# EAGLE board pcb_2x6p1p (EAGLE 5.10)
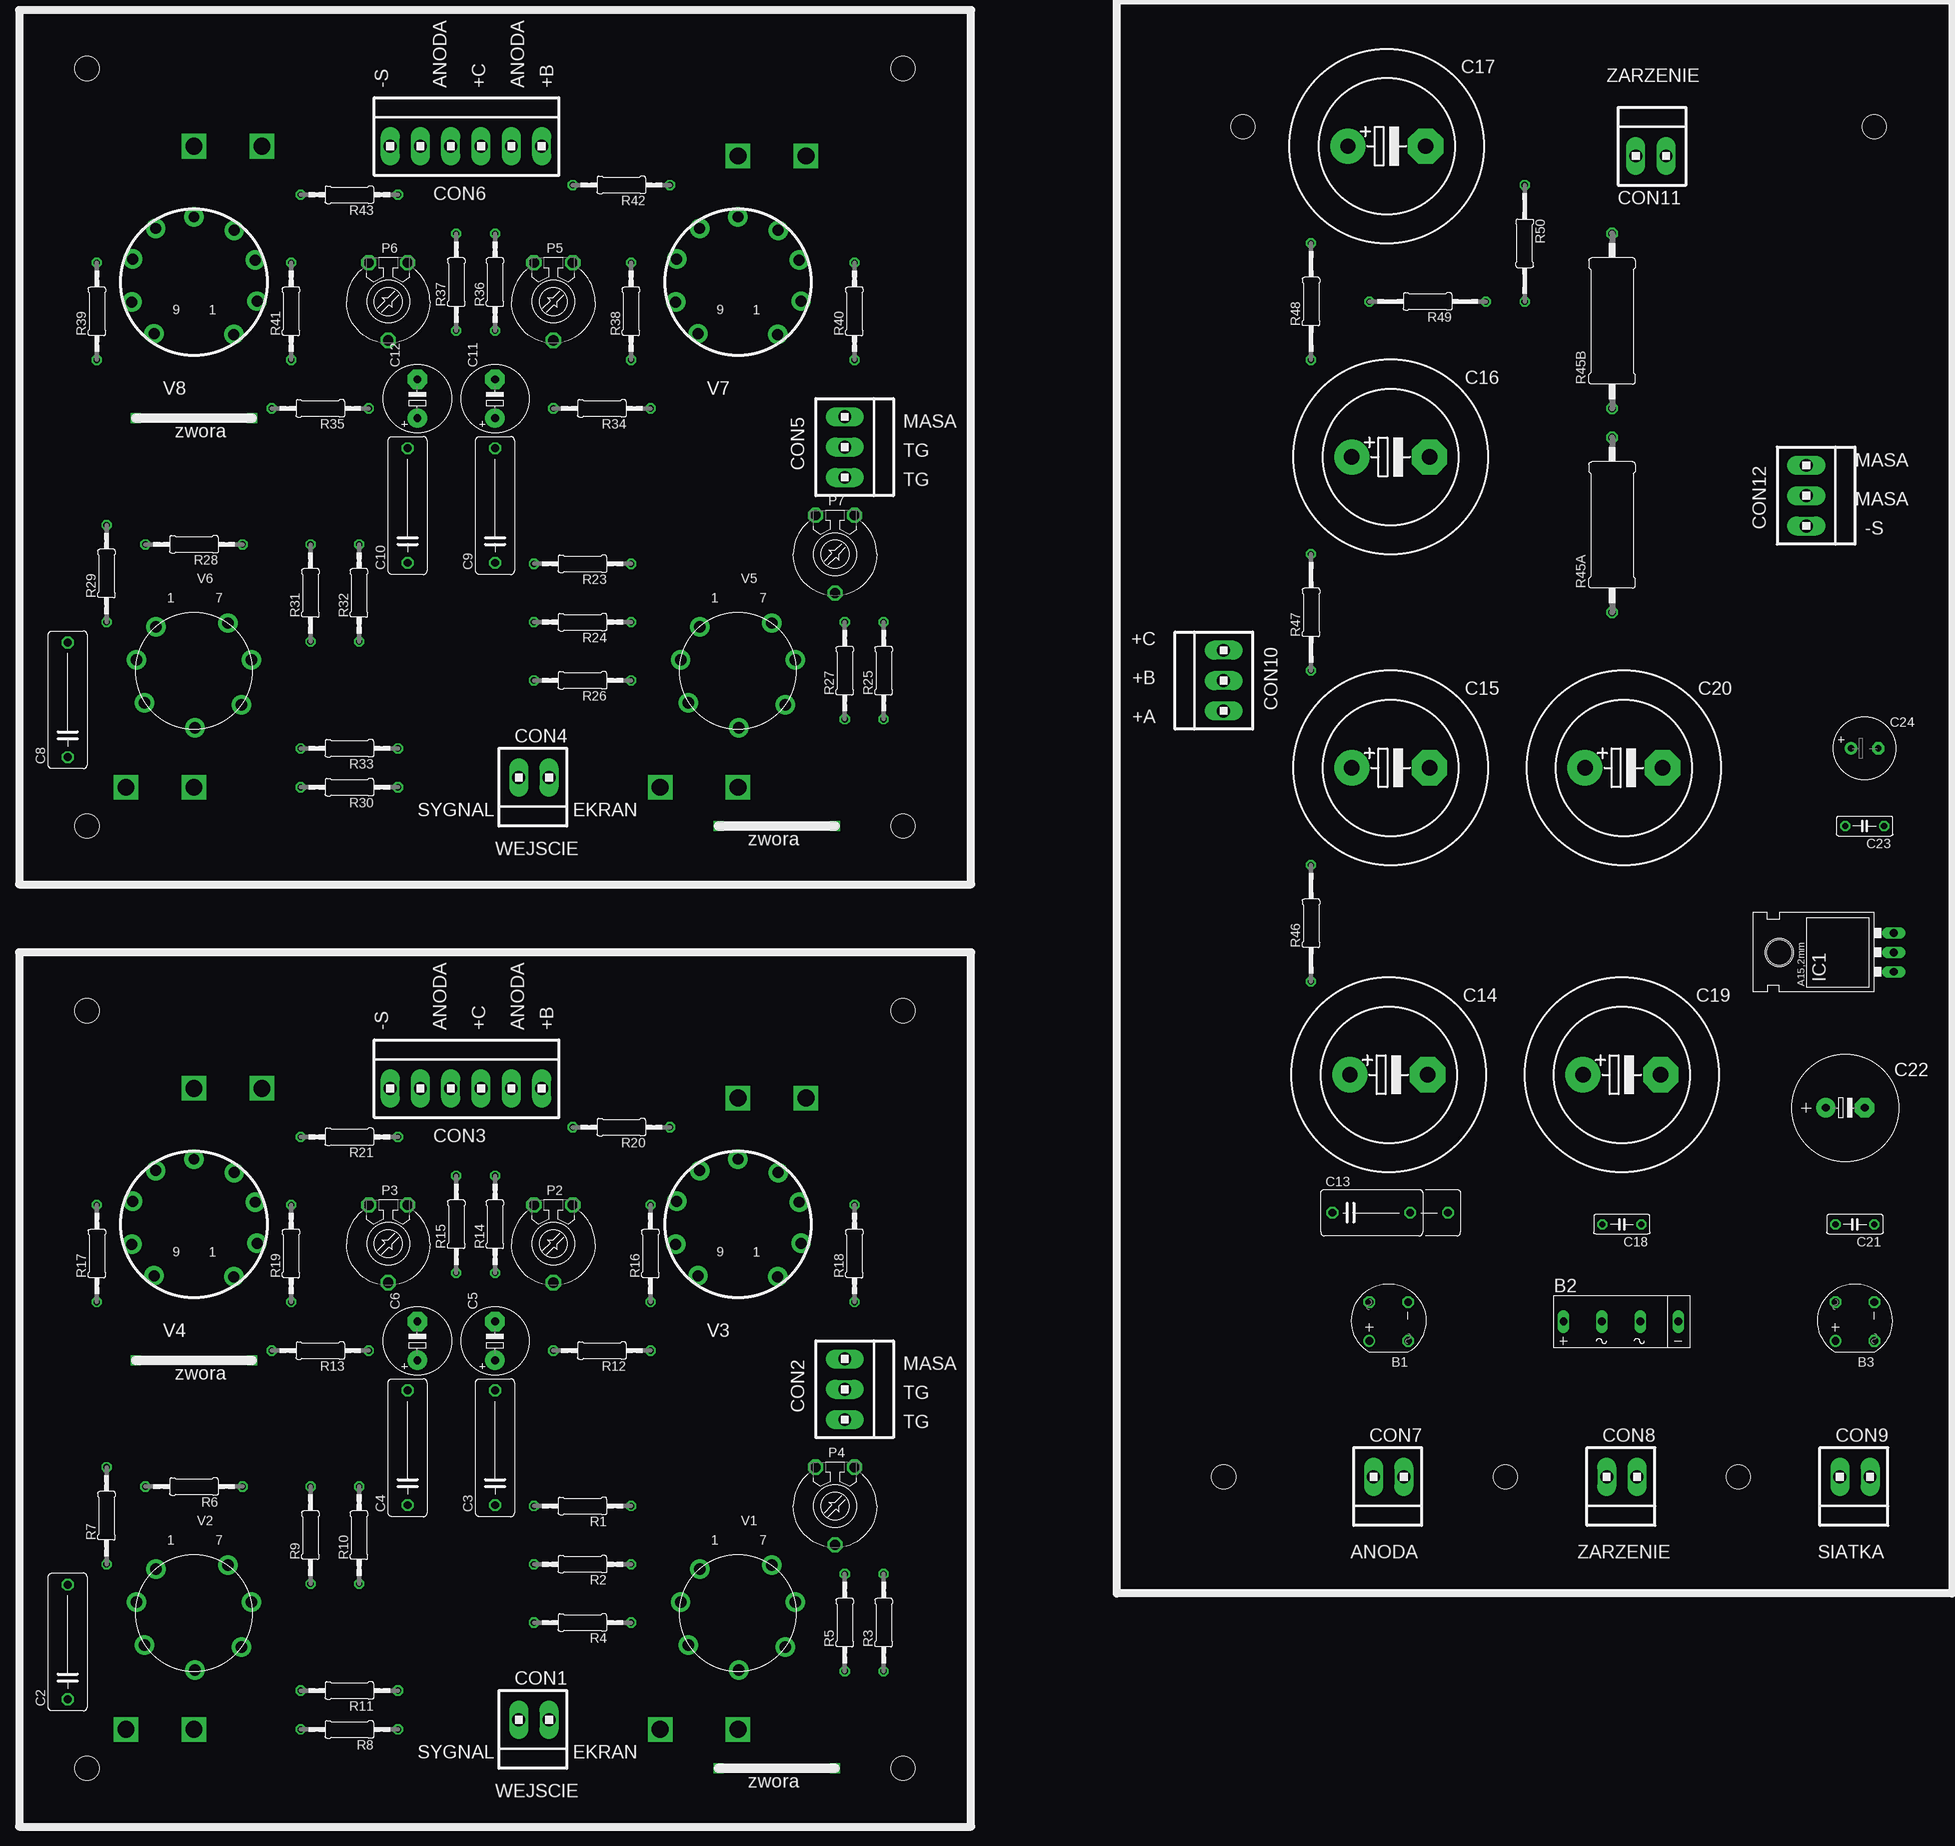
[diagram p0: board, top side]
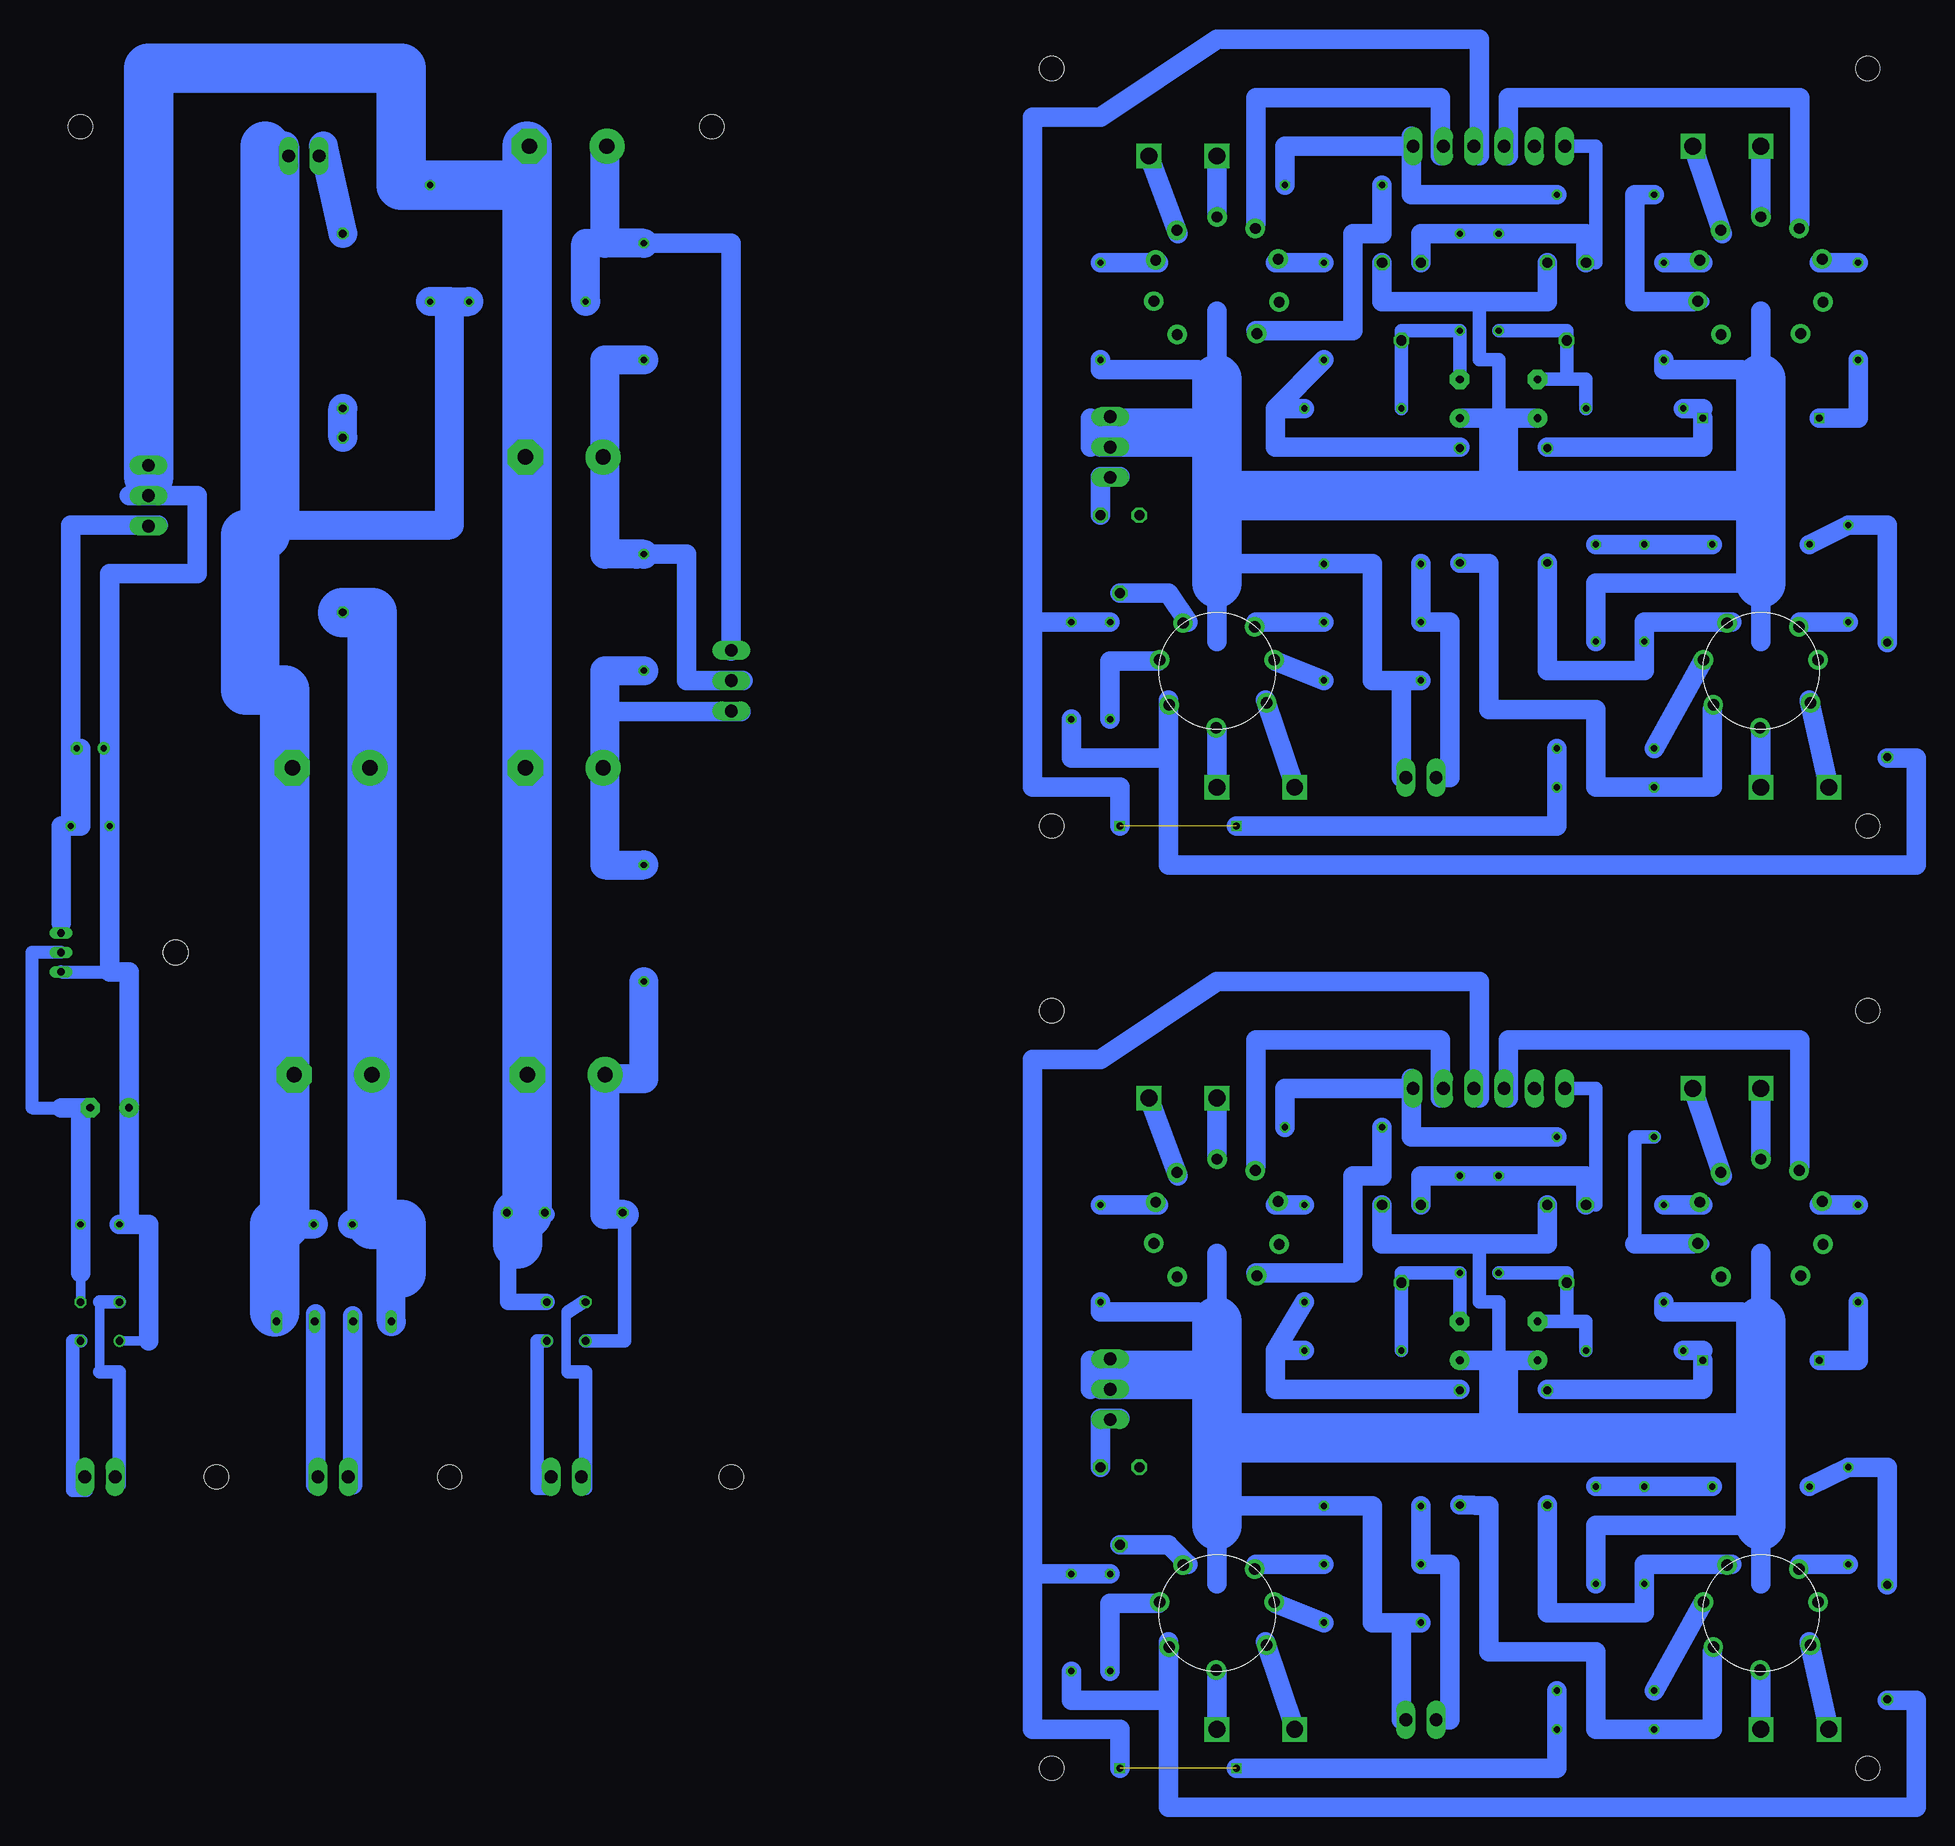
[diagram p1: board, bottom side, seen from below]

No outline drawn. Coordinates in mm, seen from the top.
Copper layers (1*16): Top 0.035mm / dielectric 1.5mm / Bottom 0.035mm
Design rules "default": minimum track width 10mil, minimum drill 24mil, track to track 8mil, track to pad 8mil, pad to pad 8mil, via to via 8mil, smd to smd 8mil, copper to edge 40mil, drill to drill 8mil, minimum pad ring 10mil, minimum via ring 8mil, stop-mask expansion 4mil, vias tented up to drill 0mil, thermal gap 10mil
Holes 3.2 mm at 116.84,12.7 10.16,111.76 116.84,111.76 10.16,12.7 116.84,135.89 10.16,234.95 116.84,234.95 10.16,135.89 195.58,50.8 226.06,50.8 243.84,227.33 161.29,227.33 158.75,50.8

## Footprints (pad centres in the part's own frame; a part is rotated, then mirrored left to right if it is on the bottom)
RB1A = drill 1.016 round: + -2.54,2.54 | drill 1.016 octagon: - 2.54,-2.54; AC1 2.54,2.54; AC2 -2.54,-2.54
2KBB-R = drill 1.016 long: + -7.62,0; - 7.391,0; AC1 -2.616,0; AC2 2.413,0
C150-054X183 = drill 1.016 octagon: 1 -7.493,0; 2 7.493,0
E5-8,5 = drill 1.016 pad 2.54 round: + -2.54,0 | drill 1.016 pad 2.54 octagon: - 2.54,0
C102_152-062X184 = drill 1.016 octagon: 1 -5.08,0; 2 5.08,0; 3 10.033,0
EB25D = drill 2.007 pad 4.597 round: + -5.08,0 | drill 2.007 pad 4.597 octagon: - 5.08,0
C050-025X075 = drill 0.813 octagon: 1 -2.54,0; 2 2.54,0
E5-13 = drill 1.016 pad 2.54 round: + -2.54,0 | drill 1.016 pad 2.54 octagon: - 2.54,0
E3,5-8 = drill 0.813 pad 1.6 round: + -1.778,0 | drill 0.813 pad 1.6 octagon: - 1.778,0
1X2MTA = drill 1.676 long: 1 1.981,0; 2 -1.981,0
1X3MTA = drill 1.676 long: 1 3.937,0; 2 -0.025,0; 3 -3.988,0
1X6MTA = drill 1.676 long: 1 9.906,0; 2 5.944,0; 3 1.981,0; 4 -1.981,0; 5 -5.944,0; 6 -9.906,0
79XXL = drill 1.016 long: GND -2.54,-3.81; IN 0,-3.81; OUT 2.54,-3.81 | hole 3.302: 0,11.176
LI10 = drill 1.321 octagon: A -2.54,-5.08; E 2.54,-5.08; S 0,5.08
0207/12 = drill 0.813 octagon: 1 -6.35,0; 2 6.35,0
0617/22 = drill 1.016 octagon: 1 -11.43,0; 2 11.43,0
0207/15 = drill 0.813 octagon: 1 -7.62,0; 2 7.62,0
MINI7_PCB = drill 1.5 pad 2.54 round: 2 4.953,-5.715; 3 7.493,-1.397; 4 6.477,4.191; 5 -0.127,7.493; 6 -6.223,4.445; 7 -4.445,-6.223; 8 -7.493,-1.397
NOVAL = drill 1.422 pad 2.54 round: 1 5.207,-6.858; 2 8.254,-2.484; 3 8.004,2.893; 4 5.258,6.77; 5 0,8.524; 6 -5.004,7.024; 7 -8.004,3.02; 8 -8.127,-2.611; 9 -5.207,-6.731

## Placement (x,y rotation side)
B1  [RB1A]  180.34,71.12 90 top
B2  [2KBB-R]  210.82,71.12 0 top
B3  [RB1A]  241.3,71.12 90 top
C2  [C150-054X183]  7.62,29.21 90 top
C3  [C150-054X183]  63.5,54.61 90 top
C4  [C150-054X183]  52.07,54.61 90 top
C5  [E5-8,5]  63.5,68.58 90 top
C6  [E5-8,5]  53.34,68.58 90 top
C8  [C150-054X183]  7.62,152.4 90 top
C9  [C150-054X183]  63.5,177.8 90 top
C10  [C150-054X183]  52.07,177.8 90 top
C11  [E5-8,5]  63.5,191.77 90 top
C12  [E5-8,5]  53.34,191.77 90 top
C13  [C102_152-062X184]  178.05,85.34 0 top
C14  [EB25D]  180.34,103.38 0 top
C15  [EB25D]  180.59,143.51 0 top
C16  [EB25D]  180.59,184.15 0 top
C17  [EB25D]  180.09,224.79 0 top
C18  [C050-025X075]  210.82,83.82 180 top
C19  [EB25D]  210.82,103.38 0 top
C20  [EB25D]  211.07,143.51 0 top
C21  [C050-025X075]  241.3,83.82 180 top
C22  [E5-13]  240.03,99.06 0 top
C23  [C050-025X075]  242.57,135.89 180 top
C24  [E3,5-8]  242.57,146.05 0 top
CON1  [1X2MTA]  68.58,19.05 180 top
CON2  [1X3MTA]  109.22,62.23 270 top
CON3  [1X6MTA]  59.69,101.6 0 top
CON4  [1X2MTA]  68.58,142.24 180 top
CON5  [1X3MTA]  109.22,185.42 270 top
CON6  [1X6MTA]  59.69,224.79 0 top
CON7  [1X2MTA]  180.34,50.8 180 top
CON8  [1X2MTA]  210.82,50.8 180 top
CON9  [1X2MTA]  241.3,50.8 180 top
CON10  [1X3MTA]  158.75,154.94 90 top
CON11  [1X2MTA]  214.63,223.52 0 top
CON12  [1X3MTA]  234.95,179.07 270 top
IC1  [79XXL]  242.57,119.38 90 top
P2  [LI10]  71.12,81.28 180 top
P3  [LI10]  49.53,81.28 180 top
P4  [LI10]  107.95,46.99 180 top
P5  [LI10]  71.12,204.47 180 top
P6  [LI10]  49.53,204.47 180 top
P7  [LI10]  107.95,171.45 180 top
R1  [0207/12]  74.93,46.99 180 top
R2  [0207/12]  74.93,39.37 180 top
R3  [0207/12]  114.3,31.75 90 top
R4  [0207/12]  74.93,31.75 180 top
R5  [0207/12]  109.22,31.75 90 top
R6  [0207/12]  24.13,49.53 180 top
R7  [0207/12]  12.7,45.72 90 top
R8  [0207/12]  44.45,17.78 180 top
R9  [0207/12]  39.37,43.18 90 top
R10  [0207/12]  45.72,43.18 90 top
R11  [0207/12]  44.45,22.86 180 top
R12  [0207/12]  77.47,67.31 180 top
R13  [0207/12]  40.64,67.31 180 top
R14  [0207/12]  63.5,83.82 90 top
R15  [0207/12]  58.42,83.82 90 top
R16  [0207/12]  83.82,80.01 90 top
R17  [0207/12]  11.43,80.01 90 top
R18  [0207/12]  110.49,80.01 90 top
R19  [0207/12]  36.83,80.01 90 top
R20  [0207/12]  80.01,96.52 180 top
R21  [0207/12]  44.45,95.25 180 top
R23  [0207/12]  74.93,170.18 180 top
R24  [0207/12]  74.93,162.56 180 top
R25  [0207/12]  114.3,156.21 90 top
R26  [0207/12]  74.93,154.94 180 top
R27  [0207/12]  109.22,156.21 90 top
R28  [0207/12]  24.13,172.72 180 top
R29  [0207/12]  12.7,168.91 90 top
R30  [0207/12]  44.45,140.97 180 top
R31  [0207/12]  39.37,166.37 90 top
R32  [0207/12]  45.72,166.37 90 top
R33  [0207/12]  44.45,146.05 180 top
R34  [0207/12]  77.47,190.5 180 top
R35  [0207/12]  40.64,190.5 180 top
R36  [0207/12]  63.5,207.01 90 top
R37  [0207/12]  58.42,207.01 90 top
R38  [0207/12]  81.28,203.2 90 top
R39  [0207/12]  11.43,203.2 90 top
R40  [0207/12]  110.49,203.2 90 top
R41  [0207/12]  36.83,203.2 90 top
R42  [0207/12]  80.01,219.71 180 top
R43  [0207/12]  44.45,218.44 180 top
R45A  [0617/22]  209.55,175.26 90 top
R45B  [0617/22]  209.55,201.93 90 top
R46  [0207/15]  170.18,123.19 90 top
R47  [0207/15]  170.18,163.83 90 top
R48  [0207/15]  170.18,204.47 90 top
R49  [0207/15]  185.42,204.47 180 top
R50  [0207/15]  198.12,212.09 270 top
V1  [MINI7_PCB]  95.25,33.02 180 top
V2  [MINI7_PCB]  24.13,33.02 180 top
V3  [NOVAL]  95.25,83.82 0 top
V4  [NOVAL]  24.13,83.82 0 top
V5  [MINI7_PCB]  95.25,156.21 180 top
V6  [MINI7_PCB]  24.13,156.21 180 top
V7  [NOVAL]  95.25,207.01 0 top
V8  [NOVAL]  24.13,207.01 0 top

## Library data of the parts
B1-B3 = rectifier
C2-C6 C8-C24 R1-R21 R23-R43 R45A R45B R46-R50 = rcl
CON1-CON12 = con-amp
IC1 = v-reg
P2-P7 = pot
V1 V2 V5 V6 = hybrid
V3 V4 V7 V8 = tubes

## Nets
S$1: R2.1
S$10: R6.1 R10.2
S$11: R7.1
S$12: R1.2 R2.2
S$13: C4.1 R9.1
S$14: R1.1 R4.2
S$15: R4.1
S$16: R3.1
S$17: C3.1 R8.2
S$18: R5.1
S$19: R10.1
S$21: R17.1
S$22: R6.2 R7.2
S$24: R11.2
S$25: R19.2
S$26: R19.1
S$27: R17.2
S$29: R18.2
S$30: R18.1
S$31: R16.2
S$32: R12.1 R16.1
S$33: R13.2
S$34: P2.A P3.A
S$35: C5.- R12.2 R14.1
S$36: C6.- R13.1 R15.1
S$38: P2.E P3.E R15.2
S$39: P4.S
S$40: P4.A
S$45: R20.2
S$46: R20.1
S$47: R21.1
S$48: R21.2
S$49: C5.+ C6.+
S$53: R3.2 R5.2 R8.1 R11.1
S$65: R24.1
S$66: R26.1
S$67: R27.1
S$70: R28.1 R32.2
S$71: C10.1 R31.1
S$72: R32.1
S$73: R29.1
S$74: R28.2 R29.2
S$75: C9.1 R30.2
S$76: R33.2
S$77: R23.2 R24.2
S$78: R23.1 R26.2
S$79: R41.2
S$80: R41.1
S$81: R39.2
S$82: R40.2
S$83: R40.1
S$84: R38.2
S$85: R34.1 R38.1
S$86: R35.2
S$87: P5.E P6.E R37.2
S$88: P7.S
S$89: P7.A
S$94: R42.2
S$95: R42.1
S$96: R43.1
S$97: R43.2
S$98: P5.A P6.A
S$99: C11.+ C12.+
S$100: C11.- R34.2 R36.1
S$101: C12.- R35.1 R37.1
S$106: R39.1
S$108: R25.2 R27.2 R30.1 R33.1
S$109: R25.1
S$113: B1.AC2
S$117: B3.AC2
S$119: B1.- R50.1
S$120: B1.+ R46.1
S$124: B3.- C22.- IC1.IN
S$125: R48.2 R49.2
S$127: R46.2 R47.1
S$128: B2.+ C18.2 R45A.1
S$129: C18.1 R49.1 R50.2
S$130: R45A.2 R45B.1
S$131: B3.AC1
S$132: R47.2 R48.1
S$133: B3.+ C21.2 C22.+ C23.2 IC1.GND
S$134: C23.1 IC1.OUT
S$137: R45B.2

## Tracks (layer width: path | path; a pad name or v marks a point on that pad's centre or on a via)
S$1
  Bottom 2.54: R2.1 90.17,39.37
S$2  (via drill 2.2)
  Bottom 2.54: v15.24,17.78 17.78,29.21
S$3  (via drill 2.2)
  Bottom 2.54: v24.13,17.78 24.13,25.4
S$4  (via drill 2.2)
  Bottom 2.54: v85.09,17.78 88.9,29.21
S$5  (via drill 2.2)
  Bottom 2.54: v95.25,17.78 95.25,25.4
S$6  (via drill 2.2)
  Bottom 2.54: 24.13,92.71 v24.13,101.6
S$7  (via drill 2.2)
  Bottom 2.54: v33.02,101.6 29.21,90.17
S$8  (via drill 2.2)
  Bottom 2.54: 95.25,92.71 v95.25,100.33
S$9  (via drill 2.2)
  Bottom 2.54: v104.14,100.33 100.33,90.17
S$10
  Bottom 2.54: R6.1 R10.2
S$11
  Bottom 2.54: R7.1 19.05,39.37
S$12
  Bottom 2.54: R1.2 R2.2 64.77,39.37 64.77,19.05 66.04,19.05
S$13
  Bottom 2.54: 27.94,39.37 39.37,39.37 R9.1 39.37,33.02 52.07,33.02 C4.1
S$14
  Bottom 2.54: 92.71,46.99 R1.1 74.93,46.99 74.93,31.75 71.12,31.75 | R4.2 71.12,31.75 | 71.12,19.05 71.12,31.75
S$15
  Bottom 2.54: R4.1 87.63,34.29
S$16
  Bottom 2.54: 7.62,21.59 3.81,21.59 3.81,7.62 101.6,7.62 101.6,21.59 | R3.1 114.3,21.59 101.6,21.59 | 101.6,21.59 101.6,29.21
S$17
  Bottom 2.54: 30.48,27.94 30.48,17.78 R8.2 45.72,17.78 45.72,27.94 59.69,27.94 59.69,46.99 C3.1
S$18
  Bottom 2.54: 102.87,34.29 109.22,34.29 R5.1
S$19
  Bottom 2.54: R10.1 45.72,44.45 26.67,44.45
S$20
  Bottom 2.54: 24.13,41.91 24.13,36.83
S$21  (via drill 0.9)
  Bottom 2.54: R17.1 11.43,66.04 v16.51,66.04
S$22
  Bottom 2.54: R6.2 R7.2 7.62,52.07 7.62,36.7
S$23
  Bottom 6.452: 95.25,55.88 95.25,71.12 | 95.25,55.88 95.25,44.45 | 24.13,55.88 95.25,55.88 | 24.13,55.88 24.13,71.12 | 24.13,44.45 24.13,55.88
S$24
  Bottom 2.54: 31.75,34.29 R11.2
S$25
  Bottom 2.54: 31.75,86.36 R19.2
S$26
  Bottom 2.54: R19.1 36.83,72.39 26.67,72.39
S$27
  Bottom 2.54: R17.2 16.51,86.36
S$28  (via drill 0.9)
  Bottom 2.54: v31.75,66.04 31.75,62.23 52.07,62.23
S$29
  Bottom 2.54: 102.87,86.36 R18.2
S$30
  Bottom 2.54: R18.1 110.49,72.39 97.79,72.39
S$31
  Bottom 2.54: R16.2 87.63,86.36
S$32
  Bottom 2.54: R16.1 87.63,67.31 | 87.63,67.31 87.63,62.23 63.5,62.23 | R12.1 87.63,67.31
S$33
  Bottom 2.54: R13.2 31.75,67.31
S$34
  Bottom 1.778: 60.96,81.28 60.96,73.66 58.42,73.66 58.42,67.31
  Bottom 2.54: P2.A 73.66,81.28 60.96,81.28 52.07,81.28 P3.A
S$35
  Bottom 1.778: C5.- R14.1 71.12,77.47 R12.2
S$36
  Bottom 1.778: R15.1 49.53,77.47 49.53,71.12 C6.- 46.99,71.12 R13.1
S$37
  Bottom 2.54: 24.13,72.39 24.13,80.01
S$38
  Bottom 2.54: P3.E 46.99,90.17 R15.2 68.58,90.17 P2.E
S$39
  Bottom 2.54: 99.06,39.37 101.6,41.91 P4.S
S$40
  Bottom 2.54: P4.A 110.49,58.42 107.95,58.42
S$41
  Bottom 2.54: 110.49,62.23 96.52,62.23
S$42
  Bottom 2.54: 110.49,66.04 97.79,66.04
S$43
  Bottom 2.54: 110.49,63.5 97.79,63.5
S$44
  Bottom 2.54: 111.76,66.04 111.76,62.23
S$45
  Bottom 2.54: 90.17,77.47 77.47,77.47 77.47,90.17 73.66,90.17 R20.2
S$46
  Bottom 2.54: R20.1 86.36,101.6 69.85,101.6
S$47
  Bottom 2.54: R21.1 69.85,95.25 69.85,102.87
S$48
  Bottom 1.778: 31.75,81.28 33.02,81.28 | 40.64,81.28 40.64,95.25 R21.2
  Bottom 2.54: 33.02,81.28 40.64,81.28
S$49
  Bottom 2.54: 58.42,66.04 57.15,66.04 | 57.15,66.04 C6.+ | 58.42,66.04 C5.+ | 58.42,58.42 58.42,66.04 | 57.15,66.04 57.15,58.42
S$50
  Bottom 2.54: 95.25,72.39 95.25,80.01
S$51
  Bottom 2.54: 19.05,91.44 19.05,107.95 57.15,107.95 57.15,100.33
S$52
  Bottom 2.54: 90.17,91.44 90.17,107.95 66.04,107.95 66.04,100.33
S$53  (via drill 0.9)  (1 unrouted)
  Bottom 2.54: 60.96,100.33 60.96,115.57 95.25,115.57 110.49,105.41 119.38,105.41 119.38,38.1 | R5.2 R3.2 119.38,38.1 | 119.38,38.1 119.38,17.78 107.95,17.78 v107.95,12.7 | R11.1 R8.1 50.8,12.7 v92.71,12.7
S$54
  Bottom 2.54: 59.69,64.77 59.69,58.42
S$55
  Bottom 2.54: 95.25,41.91 95.25,36.83
S$56
  Bottom 1.778: 49.53,101.6 45.72,101.6 45.72,86.36
S$57  (via drill 2.2)
  Bottom 2.54: v15.24,140.97 17.78,152.4
S$58  (via drill 2.2)
  Bottom 2.54: v24.13,140.97 24.13,148.59
S$59  (via drill 2.2)
  Bottom 2.54: v85.09,140.97 88.9,152.4
S$60  (via drill 2.2)
  Bottom 2.54: v95.25,140.97 95.25,148.59
S$61  (via drill 2.2)
  Bottom 2.54: 24.13,215.9 v24.13,224.79
S$62  (via drill 2.2)
  Bottom 2.54: v33.02,224.79 29.21,213.36
S$63  (via drill 2.2)
  Bottom 2.54: 95.25,215.9 v95.25,223.52
S$64  (via drill 2.2)
  Bottom 2.54: v104.14,223.52 100.33,213.36
S$65
  Bottom 2.54: R24.1 90.17,162.56
S$66
  Bottom 2.54: R26.1 87.63,157.48
S$67
  Bottom 2.54: 102.87,157.48 109.22,157.48 R27.1
S$68  (via drill 0.9)
  Bottom 2.54: v31.75,189.23 31.75,185.42 52.07,185.42
S$69
  Bottom 6.452: 95.25,179.07 95.25,194.31 | 95.25,179.07 95.25,167.64 | 24.13,179.07 95.25,179.07 | 24.13,179.07 24.13,194.31 | 24.13,167.64 24.13,179.07
S$70
  Bottom 2.54: R28.1 R32.2
S$71
  Bottom 2.54: 27.94,162.56 39.37,162.56 R31.1 39.37,156.21 52.07,156.21 C10.1
S$72
  Bottom 2.54: R32.1 45.72,167.64 26.67,167.64
S$73
  Bottom 2.54: R29.1 19.05,162.56
S$74
  Bottom 2.54: R28.2 R29.2 7.62,175.26 7.62,159.89
S$75
  Bottom 2.54: 30.48,151.13 30.48,140.97 R30.2 45.72,140.97 45.72,151.13 59.69,151.13 59.69,170.18 C9.1
S$76
  Bottom 2.54: 31.75,157.48 R33.2
S$77
  Bottom 2.54: R23.2 R24.2 64.77,162.56 64.77,142.24 66.04,142.24
S$78
  Bottom 2.54: 92.71,170.18 R23.1 74.93,170.18 74.93,154.94 71.12,154.94 | R26.2 71.12,154.94 | 71.12,142.24 71.12,154.94
S$79
  Bottom 2.54: 31.75,209.55 R41.2
S$80
  Bottom 2.54: R41.1 36.83,195.58 26.67,195.58
S$81
  Bottom 2.54: R39.2 16.51,209.55
S$82
  Bottom 2.54: 102.87,209.55 R40.2
S$83
  Bottom 2.54: R40.1 110.49,195.58 97.79,195.58
S$84
  Bottom 2.54: R38.2 87.63,209.55
S$85
  Bottom 2.54: R38.1 87.63,190.5 | 87.63,190.5 87.63,185.42 63.5,185.42 | R34.1 87.63,190.5
S$86
  Bottom 2.54: R35.2 31.75,190.5
S$87
  Bottom 2.54: P6.E 46.99,213.36 R37.2 68.58,213.36 P5.E
S$88
  Bottom 2.54: 99.06,162.56 101.6,166.37 P7.S
S$89
  Bottom 2.54: P7.A 110.49,181.61 107.95,181.61
S$90
  Bottom 2.54: 110.49,185.42 96.52,185.42
S$91
  Bottom 2.54: 110.49,189.23 97.79,189.23
S$92
  Bottom 2.54: 110.49,186.69 97.79,186.69
S$93
  Bottom 2.54: 111.76,189.23 111.76,185.42
S$94
  Bottom 2.54: 90.17,200.66 77.47,200.66 77.47,213.36 73.66,213.36 R42.2
S$95
  Bottom 2.54: R42.1 86.36,224.79 69.85,224.79
S$96
  Bottom 2.54: R43.1 69.85,218.44 69.85,226.06
S$97
  Bottom 1.778: 31.75,204.47 33.02,204.47
  Bottom 2.54: 33.02,204.47 40.64,204.47 40.64,218.44 R43.2
S$98
  Bottom 1.778: 60.96,204.47 60.96,196.85 58.42,196.85 58.42,190.5
  Bottom 2.54: P5.A 73.66,204.47 60.96,204.47 52.07,204.47 P6.A
S$99
  Bottom 2.54: 58.42,189.23 57.15,189.23 | 57.15,189.23 C12.+ | 58.42,189.23 C11.+ | 58.42,181.61 58.42,189.23 | 57.15,189.23 57.15,181.61
S$100
  Bottom 1.778: C11.- R36.1 71.12,200.66 R34.2
S$101
  Bottom 1.778: R37.1 49.53,200.66 49.53,194.31 C12.- 46.99,194.31 R35.1
S$102
  Bottom 2.54: 24.13,195.58 24.13,203.2
S$103
  Bottom 2.54: 95.25,195.58 95.25,203.2
S$104
  Bottom 2.54: 19.05,214.63 19.05,231.14 57.15,231.14 57.15,223.52
S$105
  Bottom 2.54: 90.17,214.63 90.17,231.14 66.04,231.14 66.04,223.52
S$106  (via drill 0.9)
  Bottom 2.54: R39.1 11.43,189.23 v16.51,189.23
S$107
  Bottom 2.54: 59.69,187.96 59.69,181.61
S$108  (via drill 0.9)  (1 unrouted)
  Bottom 2.54: 60.96,223.52 60.96,238.76 95.25,238.76 110.49,228.6 119.38,228.6 119.38,162.56 | R27.2 R25.2 119.38,162.56 | 119.38,162.56 119.38,140.97 107.95,140.97 v107.95,135.89 | R33.1 R30.1 50.8,135.89 v92.71,135.89
S$109
  Bottom 2.54: 7.62,144.78 3.81,144.78 3.81,130.81 101.6,130.81 101.6,144.78 | R25.1 114.3,144.78 101.6,144.78 | 101.6,144.78 101.6,152.4
S$110
  Bottom 2.54: 24.13,165.1 24.13,160.02
S$111
  Bottom 2.54: 95.25,165.1 95.25,160.02
S$112
  Bottom 1.778: 49.53,224.79 45.72,224.79 45.72,209.55
S$113
  Bottom 1.778: B1.AC2 184.15,68.58 184.15,49.28 182.12,49.28
S$114
  Bottom 1.778: 180.09,64.52 177.8,64.52 177.8,49.28
S$115
  Bottom 2.54: 208.28,71.88 208.28,49.78
S$116
  Bottom 2.54: 213.11,72.14 213.11,49.78
S$117
  Bottom 1.778: B3.AC2 244.86,68.58 244.86,49.02 243.08,49.02
S$118
  Bottom 1.778: 241.3,64.52 238.76,64.52 238.76,49.78
S$119
  Bottom 2.184: B1.- 187.96,73.66 187.96,85.09 186.69,85.09 | 182.88,85.09 185.42,85.09
  Bottom 3.81: 185.42,85.09 185.42,219.71 | 185.42,219.71 185.42,224.79 185.42,226.06 | 201.93,234.95 200.66,234.95 200.66,219.71 R50.1 187.96,219.71 185.42,219.71
  Bottom 6.452: 234.95,181.61 234.95,234.95 201.93,234.95 201.93,219.71 187.96,219.71 | 185.42,224.79 185.42,85.09 186.69,85.09 186.69,81.28
S$120
  Bottom 1.778: B1.+ 172.72,68.58 172.72,85.09
  Bottom 3.81: 172.72,85.09 175.26,85.09 175.26,102.87 170.18,102.87 R46.1
S$121
  Bottom 1.778: 178.05,73.66 180.09,72.39
S$122
  Bottom 1.27: 180.34,64.77 180.34,72.39
S$123
  Bottom 2.54: 157.48,150.88 174.5,150.88
S$124
  Bottom 1.27: B3.- 243.84,77.47
  Bottom 1.676: IC1.IN 250.19,119.38 250.19,99.06 243.84,99.06
  Bottom 2.54: 246.38,99.06 243.84,99.06 | 243.84,99.06 C22.- | 243.84,77.47 243.84,99.06
S$125
  Bottom 2.54: 176.53,212.09 R48.2 158.75,212.09 158.75,158.75
  Bottom 3.81: R48.2 175.26,212.09 175.26,224.79 | R49.2 177.8,212.09 176.53,212.09
S$127
  Bottom 2.54: 175.26,143.51 176.02,143.51
  Bottom 3.81: R47.1 175.26,156.21 175.26,143.51 175.26,130.81 R46.2
S$128
  Bottom 3.81: B2.+ 203.2,83.82 205.74,83.82 C18.2
  Bottom 6.452: 201.93,77.47 201.93,83.82 205.74,83.82 205.74,163.83 R45A.1
S$129
  Bottom 3.81: 218.44,71.12 218.44,72.39 | 217.17,83.82 215.9,83.82 | C18.1 215.9,83.82 | 215.9,83.82 215.9,153.67 219.71,153.67 219.71,173.99 219.71,175.26 195.58,175.26 195.58,204.47 | 195.58,204.47 R50.2 | 195.58,204.47 R49.1
  Bottom 6.452: 218.44,72.39 218.44,83.82 217.17,83.82 217.17,153.67 222.25,153.67 222.25,173.99 219.71,173.99 219.71,224.79
S$130
  Bottom 3.81: R45A.2 R45B.1
S$131
  Bottom 1.27: 241.3,73.66 241.3,64.77
  Bottom 1.778: 241.3,73.66 B3.AC1
S$132
  Bottom 2.54: 157.23,154.94 164.59,154.94 164.59,171.45 171.2,171.45
  Bottom 3.81: R47.2 171.2,171.45 175.26,171.45 175.26,196.85 R48.1
S$133
  Bottom 1.27: 234.95,68.58 B3.+ | 234.95,83.82 237.49,83.82 C22.+ 237.49,116.84 | 240.03,116.84 C23.2 240.03,146.05
  Bottom 1.676: IC1.GND 240.03,116.84
  Bottom 2.54: 234.95,68.58 234.95,83.82 C21.2 237.49,83.82 237.49,116.84 240.03,116.84 240.03,146.05 240.03,168.91 228.6,168.91 228.6,179.07 237.49,179.07
S$134
  Bottom 1.27: 243.84,135.89 C23.1 246.38,135.89 | IC1.OUT 246.38,123.19
  Bottom 2.54: 246.38,123.19 246.38,135.89 243.84,135.89 243.84,146.05
S$136
  Bottom 2.54: 209.3,213.61 211.84,224.79
S$137
  Bottom 3.81: 212.09,224.79 R45B.2
S$138
  Bottom 3.81: 217.17,224.79 217.17,176.53
S$139
  Bottom 2.54: 245.11,137.16 245.11,175.26 233.68,175.26

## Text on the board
tNames: ZARZENIE | -S | ANODA | +C | ANODA | +B | MASA | zwora | TG | MASA | TG | MASA | -S | +C | +B | +A | SYGNAL | EKRAN | zwora | WEJSCIE | -S | ANODA | +C | ANODA | +B | MASA | zwora | TG | TG | ANODA | ZARZENIE | SIATKA | SYGNAL | EKRAN | zwora | WEJSCIE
